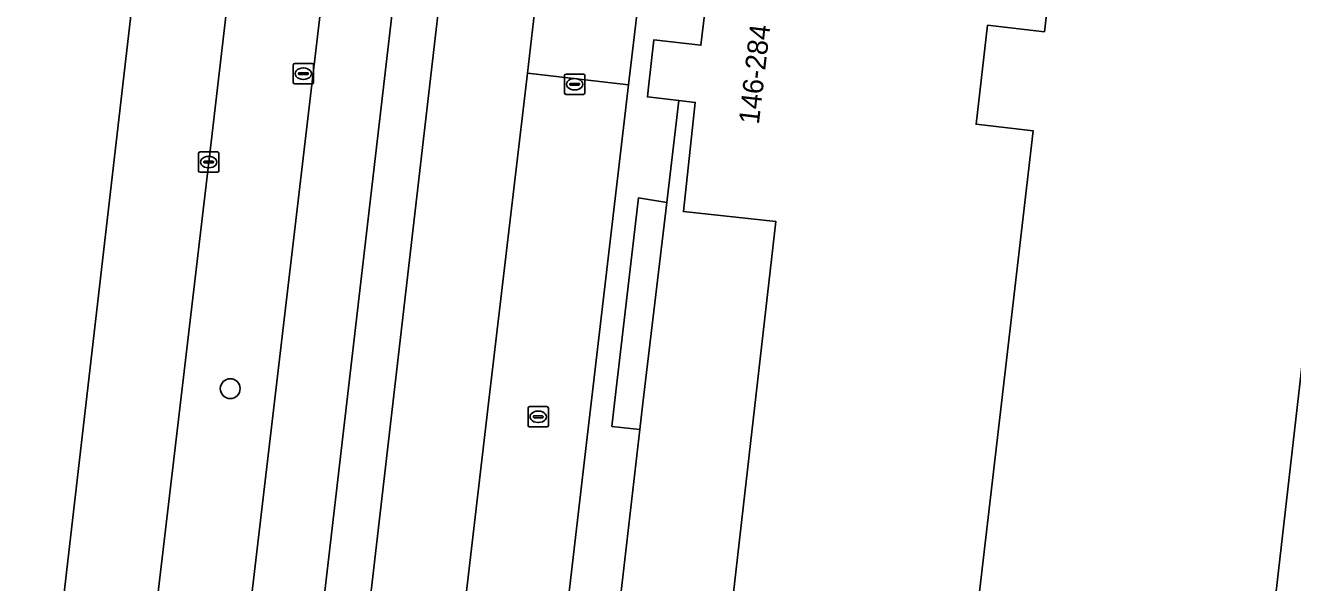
# Model space of a CAD drawing. Extents: x 161241 to 161758, y 384138 to 384885.
# Drawn here: x 161277.3 to 161339.7, y 384491.2 to 384518.6 of the extents above; entities that cross this region are included whole.
import ezdxf

# ---------------------------------------------------------------- set-up
doc = ezdxf.new("R2010")
doc.units = 0
for name, color, linetype in [('IMGEO_Berm_groen', 7, 'Continuous'), ('IMGEO_Boom', 7, 'Continuous'), ('IMGEO_Erf', 7, 'Continuous'), ('IMGEO_Fietspad_gesloten', 7, 'Continuous'), ('IMGEO_Kolk', 7, 'Continuous'), ('IMGEO_OVBaan_gesloten', 7, 'Continuous'), ('IMGEO_Pand', 7, 'Continuous'), ('IMGEO_Pand_nummerreeks', 7, 'Continuous'), ('IMGEO_Pand_overbouw', 7, 'Continuous'), ('IMGEO_Parkeervlak_open', 7, 'Continuous'), ('IMGEO_Rijbaan_lokaal_open', 7, 'Continuous'), ('IMGEO_Rioolput', 7, 'Continuous'), ('IMGEO_Voetpad_open', 7, 'Continuous')]:
    doc.layers.add(name, color=color, linetype=linetype)

msp = doc.modelspace()

# ---------------------------------------------------------------- linework, layer by layer
at = {"layer": 'IMGEO_Berm_groen'}
msp.add_lwpolyline([(161278.307, 384403.15), (161286.202, 384471.417), (161293.323, 384531.813), (161296.311, 384554.647), (161300.999, 384591.473), (161306.453, 384637.728), (161301.117, 384638.364), (161300.355, 384631.67), (161297.994, 384611.38), (161295.634, 384591.049), (161293.255, 384570.775), (161290.848, 384550.464), (161288.707, 384532.15), (161288.472, 384530.133), (161286.341, 384511.851), (161283.768, 384490.025), (161281.583, 384471.698), (161279.185, 384451.364)], dxfattribs=at)
at = {"layer": 'IMGEO_Boom'}
msp.add_circle((161287.402, 384500.72), 0.489, dxfattribs=at)
at = {"layer": 'IMGEO_Erf'}
for points in [[(161341.28, 384633.76), (161338.47, 384631.536), (161337.879, 384631.605), (161330.356, 384566.963), (161329.778, 384567.03), (161329.206, 384562.128), (161332.52, 384561.741), (161327.448, 384518.254), (161324.658, 384518.579), (161324.09, 384513.711), (161326.898, 384513.383), (161325.337, 384500), (161321.817, 384469.82), (161318.472, 384470.21), (161317.897, 384465.282), (161318.52, 384465.21), (161310.988, 384400.64)], [(161332.131, 384432.245), (161332.897, 384438.907), (161336.632, 384471.394), (161336.946, 384474.139), (161340.403, 384504.377), (161340.647, 384506.515), (161340.82, 384506.489), (161349.943, 384584.816), (161350.191, 384586.943), (161382.92, 384583.217)]]:
    msp.add_lwpolyline(points, dxfattribs=at)
msp.add_lwpolyline([(161314.24, 384508.93), (161309.696, 384509.419), (161310.273, 384514.788), (161309.469, 384514.874), (161308.875, 384509.871), (161307.703, 384500), (161307.55, 384498.708), (161306.361, 384488.486), (161305.051, 384477.227), (161304.42, 384471.807), (161306.87, 384471.521), (161309.921, 384471.176)], close=True, dxfattribs=at)
at = {"layer": 'IMGEO_Fietspad_gesloten'}
for points in [[(161258.742, 384157.135), (161260.876, 384184.71), (161262.854, 384210.484), (161266.448, 384261.586), (161267.146, 384270.325), (161268.291, 384284.663), (161268.569, 384287.683), (161268.583, 384287.814), (161270.005, 384301.578), (161270.134, 384303.063), (161273.019, 384327.449), (161276.269, 384355.259), (161281.811, 384402.692), (161289.671, 384470.352), (161296.755, 384531.182), (161299.82, 384554.106), (161304.483, 384590.763), (161310.58, 384642.356), (161311.044, 384646.284), (161311.712, 384651.942), (161311.774, 384652.424)], [(161308.263, 384652.525), (161306.453, 384637.728), (161300.999, 384591.473), (161296.311, 384554.647), (161293.323, 384531.813), (161286.202, 384471.417), (161278.307, 384403.15), (161275.866, 384382.258), (161272.845, 384356.399), (161269.542, 384328.133), (161269.524, 384327.978), (161266.559, 384302.554), (161265.412, 384302.67), (161262.065, 384303.024), (161261.777, 384300.445), (161262.272, 384300.399), (161264.329, 384300.231)]]:
    msp.add_lwpolyline(points, dxfattribs=at)
at = {"layer": 'IMGEO_Kolk'}
for p, q in [((161303.845, 384515.251), (161303.845, 384516.103)), ((161303.92, 384516.177), (161304.772, 384516.177)), ((161304.846, 384516.103), (161304.846, 384515.251)), ((161304.104, 384515.671), (161304.104, 384515.683)), ((161304.542, 384515.634), (161304.144, 384515.634)), ((161304.147, 384515.72), (161304.545, 384515.72)), ((161304.333, 384515.957), (161304.358, 384515.957)), ((161304.588, 384515.683), (161304.588, 384515.671)), ((161304.772, 384515.177), (161303.92, 384515.177)), ((161304.356, 384515.397), (161304.331, 384515.397)), ((161285.915, 384512.351), (161286.767, 384512.351)), ((161285.84, 384511.425), (161285.84, 384512.277)), ((161286.099, 384511.845), (161286.099, 384511.857)), ((161286.537, 384511.808), (161286.139, 384511.808)), ((161286.142, 384511.894), (161286.54, 384511.894)), ((161286.328, 384512.131), (161286.353, 384512.131)), ((161286.583, 384511.857), (161286.583, 384511.845)), ((161286.841, 384512.277), (161286.841, 384511.425)), ((161286.767, 384511.351), (161285.915, 384511.351)), ((161286.351, 384511.571), (161286.326, 384511.571)), ((161302.049, 384498.91), (161302.049, 384499.762)), ((161302.124, 384499.836), (161302.976, 384499.836)), ((161302.308, 384499.33), (161302.308, 384499.342)), ((161302.746, 384499.293), (161302.348, 384499.293)), ((161302.351, 384499.379), (161302.749, 384499.379)), ((161302.537, 384499.616), (161302.562, 384499.616)), ((161302.792, 384499.342), (161302.792, 384499.33)), ((161303.05, 384499.762), (161303.05, 384498.91)), ((161302.976, 384498.836), (161302.124, 384498.836)), ((161302.56, 384499.056), (161302.535, 384499.056))]:
    msp.add_line(p, q, dxfattribs=at)
for points in [[(161303.845, 384515.251), (161303.845, 384516.103)], [(161303.92, 384516.177), (161304.772, 384516.177)], [(161304.846, 384516.103), (161304.846, 384515.251)], [(161304.772, 384515.177), (161303.92, 384515.177)], [(161285.915, 384512.351), (161286.767, 384512.351)], [(161285.84, 384511.425), (161285.84, 384512.277)], [(161286.841, 384512.277), (161286.841, 384511.425)], [(161286.767, 384511.351), (161285.915, 384511.351)], [(161302.049, 384498.91), (161302.049, 384499.762)], [(161302.124, 384499.836), (161302.976, 384499.836)], [(161303.05, 384499.762), (161303.05, 384498.91)], [(161302.976, 384498.836), (161302.124, 384498.836)]]:
    msp.add_lwpolyline(points, dxfattribs=at)
for centre, radius, start, end in [((161303.922, 384516.101), 0.0765, 91.55205, 178.44795), ((161303.922, 384516.101), 0.0765, 91.55205, 178.44795), ((161304.77, 384516.101), 0.0765, 1.55205, 88.44795), ((161304.77, 384516.101), 0.0765, 1.55205, 88.44795), ((161304.144, 384515.68), 0.0403, 85.87752, 175.75265), ((161304.141, 384515.67), 0.0366, 178.93798, 274.71019), ((161304.545, 384515.677), 0.043, 264.86636, 352.45326), ((161304.549, 384515.682), 0.0386, 1.73085, 96.63898), ((161303.922, 384515.253), 0.0765, 181.55205, 268.44795), ((161303.922, 384515.253), 0.0765, 181.55205, 268.44795), ((161304.77, 384515.253), 0.0765, 271.55205, 358.44795), ((161304.77, 384515.253), 0.0765, 271.55205, 358.44795), ((161285.917, 384512.275), 0.0765, 91.55205, 178.44795), ((161285.917, 384512.275), 0.0765, 91.55205, 178.44795), ((161286.765, 384512.275), 0.0765, 1.55205, 88.44795), ((161286.765, 384512.275), 0.0765, 1.55205, 88.44795), ((161286.139, 384511.854), 0.0403, 85.87752, 175.75265), ((161286.136, 384511.844), 0.0366, 178.93798, 274.71019), ((161286.54, 384511.851), 0.043, 264.86636, 352.45326), ((161286.544, 384511.856), 0.0386, 1.73085, 96.63898), ((161285.917, 384511.427), 0.0765, 181.55205, 268.44795), ((161285.917, 384511.427), 0.0765, 181.55205, 268.44795), ((161286.765, 384511.427), 0.0765, 271.55205, 358.44795), ((161286.765, 384511.427), 0.0765, 271.55205, 358.44795), ((161302.126, 384499.76), 0.0765, 91.55205, 178.44795), ((161302.126, 384499.76), 0.0765, 91.55205, 178.44795), ((161302.348, 384499.339), 0.0403, 85.87752, 175.75265), ((161302.345, 384499.329), 0.0366, 178.93798, 274.71019), ((161302.749, 384499.336), 0.043, 264.86636, 352.45326), ((161302.753, 384499.341), 0.0386, 1.73085, 96.63898), ((161302.974, 384499.76), 0.0765, 1.55205, 88.44795), ((161302.974, 384499.76), 0.0765, 1.55205, 88.44795), ((161302.126, 384498.912), 0.0765, 181.55205, 268.44795), ((161302.126, 384498.912), 0.0765, 181.55205, 268.44795), ((161302.974, 384498.912), 0.0765, 271.55205, 358.44795), ((161302.974, 384498.912), 0.0765, 271.55205, 358.44795)]:
    msp.add_arc(centre, radius, start, end, dxfattribs=at)
for centre, major_axis, ratio, start_param, end_param in [((161304.332, 384515.677), (-0.387, 0.002), 0.722429, 4.712389, 7.853982), ((161304.357, 384515.677), (-0.39, 0.002), 0.717154, 1.570796, 4.712389), ((161286.327, 384511.851), (-0.387, 0.002), 0.722429, 4.712389, 7.853982), ((161286.352, 384511.851), (-0.39, 0.002), 0.717154, 1.570796, 4.712389), ((161302.536, 384499.336), (-0.387, 0.002), 0.722429, 4.712389, 7.853982), ((161302.561, 384499.336), (-0.39, 0.002), 0.717154, 1.570796, 4.712389)]:
    msp.add_ellipse(centre, major_axis=major_axis, ratio=ratio, start_param=start_param, end_param=end_param, dxfattribs=at)
at = {"layer": 'IMGEO_OVBaan_gesloten'}
for points in [[(161312.353, 384812.006), (161309.921, 384834.117), (161309.774, 384835.487), (161309.446, 384838.541), (161309.033, 384842.394), (161308.618, 384846.264), (161308.42, 384848.049), (161305.427, 384848.093), (161310.221, 384805.365), (161309.046, 384772.256), (161307.924, 384740.658), (161299.466, 384666.717), (161288.788, 384573.374), (161256.675, 384295.749), (161254.709, 384278.75), (161244.663, 384173.474), (161243.814, 384162.675), (161243.598, 384159.911), (161243.455, 384158.862), (161242.942, 384154.711), (161242.923, 384154.593), (161242.753, 384153.458), (161241.269, 384137.91)], [(161261.738, 384300.096), (161261.777, 384300.445), (161262.065, 384303.024), (161262.902, 384310.522), (161264.916, 384328.431), (161267.197, 384347.869), (161269.457, 384367.164), (161271.789, 384387.356), (161274.112, 384407.478), (161276.721, 384430.069), (161279.185, 384451.364), (161281.583, 384471.698), (161283.768, 384490.025), (161286.341, 384511.851), (161288.472, 384530.133), (161288.707, 384532.15), (161290.848, 384550.464), (161293.255, 384570.775), (161295.634, 384591.049), (161297.994, 384611.38), (161300.355, 384631.67), (161301.117, 384638.364), (161302.766, 384651.987), (161302.856, 384653.145)]]:
    msp.add_lwpolyline(points, dxfattribs=at)
at = {"layer": 'IMGEO_Pand'}
msp.add_lwpolyline([(161324.658, 384518.579), (161327.448, 384518.254), (161332.52, 384561.741), (161329.206, 384562.128), (161320.568, 384563.129), (161315.768, 384522.059), (161315.485, 384519.641), (161310.857, 384520.181), (161310.556, 384517.594), (161308.245, 384517.862), (161307.974, 384515.528), (161307.919, 384515.054), (161309.469, 384514.874), (161310.273, 384514.788), (161309.696, 384509.419), (161314.24, 384508.93), (161309.921, 384471.176), (161318.472, 384470.21), (161321.817, 384469.82), (161325.337, 384500), (161326.898, 384513.383), (161324.09, 384513.711)], close=True, dxfattribs=at)
at = {"layer": 'IMGEO_Pand_overbouw'}
msp.add_lwpolyline([(161314.24, 384508.93), (161309.696, 384509.419), (161310.273, 384514.788), (161309.469, 384514.874), (161308.875, 384509.871), (161307.703, 384500), (161307.55, 384498.708), (161306.361, 384488.486), (161305.051, 384477.227), (161304.42, 384471.807), (161306.87, 384471.521), (161309.921, 384471.176)], close=True, dxfattribs=at)
at = {"layer": 'IMGEO_Parkeervlak_open'}
for points in [[(161300.111, 384500), (161302.017, 384516.22), (161302.57, 384520.925), (161303.783, 384531.252)], [(161302.672, 384530.431), (161299.265, 384530.92), (161299.086, 384530.946), (161298.986, 384530.962), (161298.968, 384530.827), (161291.483, 384466.168), (161291.644, 384466.15), (161295.04, 384465.761), (161296.054, 384465.353), (161299.421, 384494.132), (161300.111, 384500)]]:
    msp.add_lwpolyline(points, dxfattribs=at)
at = {"layer": 'IMGEO_Rijbaan_lokaal_open'}
msp.add_lwpolyline([(161307.548, 384520.344), (161302.57, 384520.925), (161302.017, 384516.22), (161306.995, 384515.642)], close=True, dxfattribs=at)
msp.add_lwpolyline([(161300.387, 384455.527), (161300.369, 384455.413), (161297.775, 384432.519), (161294.636, 384405.626), (161294.174, 384401.499), (161299.115, 384400.923), (161300.959, 384416.574), (161304.65, 384447.935), (161306.178, 384461.35), (161301.344, 384467.341), (161304.927, 384498.052), (161305.156, 384500), (161306.995, 384515.642), (161302.017, 384516.22), (161300.111, 384500), (161299.421, 384494.132), (161296.054, 384465.353), (161296.293, 384465.043), (161297.392, 384463.094), (161298.875, 384460.463), (161299.888, 384458.667)], dxfattribs=at)
at = {"layer": 'IMGEO_Rioolput'}
for p, q in [((161290.499, 384515.771), (161290.499, 384516.623)), ((161290.574, 384516.697), (161291.426, 384516.697)), ((161290.758, 384516.191), (161290.758, 384516.203)), ((161291.196, 384516.154), (161290.798, 384516.154)), ((161290.801, 384516.24), (161291.199, 384516.24)), ((161290.987, 384516.477), (161291.012, 384516.477)), ((161291.242, 384516.203), (161291.242, 384516.191)), ((161291.5, 384516.623), (161291.5, 384515.771)), ((161291.426, 384515.697), (161290.574, 384515.697)), ((161291.01, 384515.917), (161290.985, 384515.917))]:
    msp.add_line(p, q, dxfattribs=at)
for points in [[(161290.499, 384515.771), (161290.499, 384516.623)], [(161290.574, 384516.697), (161291.426, 384516.697)], [(161291.5, 384516.623), (161291.5, 384515.771)], [(161291.426, 384515.697), (161290.574, 384515.697)]]:
    msp.add_lwpolyline(points, dxfattribs=at)
for centre, radius, start, end in [((161290.576, 384516.621), 0.0765, 91.55205, 178.44795), ((161290.576, 384516.621), 0.0765, 91.55205, 178.44795), ((161290.798, 384516.2), 0.0403, 85.87752, 175.75265), ((161290.795, 384516.19), 0.0366, 178.93798, 274.71019), ((161291.199, 384516.197), 0.043, 264.86636, 352.45326), ((161291.203, 384516.202), 0.0386, 1.73085, 96.63898), ((161291.424, 384516.621), 0.0765, 1.55205, 88.44795), ((161291.424, 384516.621), 0.0765, 1.55205, 88.44795), ((161290.576, 384515.773), 0.0765, 181.55205, 268.44795), ((161290.576, 384515.773), 0.0765, 181.55205, 268.44795), ((161291.424, 384515.773), 0.0765, 271.55205, 358.44795), ((161291.424, 384515.773), 0.0765, 271.55205, 358.44795)]:
    msp.add_arc(centre, radius, start, end, dxfattribs=at)
for centre, major_axis, ratio, start_param, end_param in [((161290.986, 384516.197), (-0.387, 0.002), 0.722429, 4.712389, 7.853982), ((161291.011, 384516.197), (-0.39, 0.002), 0.717154, 1.570796, 4.712389)]:
    msp.add_ellipse(centre, major_axis=major_axis, ratio=ratio, start_param=start_param, end_param=end_param, dxfattribs=at)
at = {"layer": 'IMGEO_Voetpad_open'}
for points in [[(161311.774, 384652.424), (161311.712, 384651.942), (161311.044, 384646.284), (161310.58, 384642.356), (161304.483, 384590.763), (161299.82, 384554.106), (161296.755, 384531.182), (161289.671, 384470.352), (161281.811, 384402.692), (161276.269, 384355.259), (161273.019, 384327.449), (161270.134, 384303.063), (161270.005, 384301.578)], [(161366.853, 384643.333), (161336.314, 384646.823), (161333.288, 384644.347), (161331.082, 384642.543), (161326.899, 384639.121), (161324.303, 384616.759), (161323.425, 384609.052), (161321.313, 384590.613), (161319.366, 384573.967), (161313.194, 384569.245), (161309.149, 384533.964), (161307.548, 384520.344), (161306.995, 384515.642), (161305.156, 384500), (161304.927, 384498.052), (161301.344, 384467.341), (161306.178, 384461.35), (161304.65, 384447.935)], [(161289.844, 384452.553), (161298.017, 384459.712), (161296.049, 384461.925), (161290.446, 384457.047), (161291.483, 384466.168), (161298.968, 384530.827), (161298.986, 384530.962), (161299.549, 384535.196), (161302.052, 384554.002), (161303.794, 384567.742), (161305.062, 384577.742)], [(161300.962, 384399.132), (161308.794, 384466.279), (161306.691, 384466.524), (161306.965, 384468.879), (161306.567, 384468.925), (161306.87, 384471.521), (161304.42, 384471.807), (161305.051, 384477.227), (161303.676, 384477.383), (161304.923, 384488.649), (161306.361, 384488.486), (161307.55, 384498.708), (161306.177, 384498.861), (161306.309, 384500), (161307.484, 384510.101), (161308.875, 384509.871), (161309.469, 384514.874), (161307.919, 384515.054), (161307.974, 384515.528), (161308.245, 384517.862), (161310.556, 384517.594), (161310.857, 384520.181)]]:
    msp.add_lwpolyline(points, dxfattribs=at)
for points in [[(161307.484, 384510.101), (161306.309, 384500), (161306.177, 384498.861), (161307.55, 384498.708), (161307.703, 384500), (161308.875, 384509.871)], [(161341.704, 384504.225), (161340.403, 384504.377), (161336.946, 384474.139), (161338.179, 384473.999)]]:
    msp.add_lwpolyline(points, close=True, dxfattribs=at)

# ---------------------------------------------------------------- texts
at = {"layer": 'IMGEO_Pand_nummerreeks'}
msp.add_text('146-284', height=1, rotation=83.34817, dxfattribs=at).set_placement((161313.401, 384513.676))

doc.saveas('drawing.dxf')
